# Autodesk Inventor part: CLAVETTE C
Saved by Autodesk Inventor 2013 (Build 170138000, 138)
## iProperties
Created: 2012-12
Part Number: CLAVETTE C
Material: Générique
Document SubType Name: Modeling
Designer: jost thierry
Density: 1 g/cm^3
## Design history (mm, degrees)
node "CLAVETTE C1"
node "CLAVETTE C"
node "Base1"
